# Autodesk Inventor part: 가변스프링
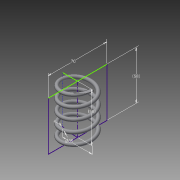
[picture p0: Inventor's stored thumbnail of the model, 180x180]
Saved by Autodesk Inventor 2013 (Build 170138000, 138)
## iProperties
Created: 2015-03
Part Number: 가변스프링
Material: 일반
Document SubType Name: Modeling
Designer: Administrator
Density: 1 g/cm^3
Mass: 6.07317 g
Surface Area: 62.0098 cm^2
Volume: 6.07317 cm^3
Author: Administrator
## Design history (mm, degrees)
sketch "스케치2"
  geometry: L1 (0, 0)-(17.5, 0); L2 (17.5, 0)-(17.5, 43.5); L3 (17.5, 43.5)-(0, 43.5); L4 (0, 43.5)-(0, 0); C1 r 2 at (17.5, 0); 1 further point
  constraints: 8 end point, 2 parallel, 1 centre point, 1 coincident, 1 horizontal, 1 perpendicular
  dimensions: "d0" = 35 diameter of L2 L4; "d2" = 43.5 distance of L3.end L1.start (derived); "d3" = 4 diameter of C1
feature "코일1" sketch "스케치2" pitch "d4" = 10; turns "d6" = 4.5; dims "d5" = 43.5 (= d2), "d7" = 0, angle "d8" = 90 deg, angle "d9" = 90 deg, "d10" = 0, "d11" = 0
sketch "스케치5"
  geometry: L1 (0, -35)-(43.5, -35); L2 (43.5, -35)-(43.5, 35); L3 (43.5, 35)-(0, 35); L4 (0, 35)-(0, -35); 2 further points
  constraints: 8 end point, 2 parallel, 1 coincident, 1 horizontal, 1 midpoint, 1 perpendicular
  dimensions: "d12" = 70 distance of L1.end L2.end; "d14" = 43.5 distance of L2.end L3.end (derived)
extrude "돌출1" sketch "스케치5" stored distance "d15" = 0; taper "d16" = 0 deg
node "솔리드1"
